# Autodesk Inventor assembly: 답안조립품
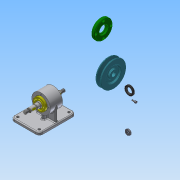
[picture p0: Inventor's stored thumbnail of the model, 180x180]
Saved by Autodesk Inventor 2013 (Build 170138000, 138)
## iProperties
Created: 2019-09
Part Number: 답안조립품
Document SubType Name: Assembly
Designer: Administrator
Author: Administrator
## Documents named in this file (10)
- C:\Users\Administrator\Desktop\490904V1052\답안조립품.iam
- C:\Users\Administrator\Desktop\490904V1052\본체.ipt
- C:\Users\Administrator\Desktop\490904V1052\V-벨트풀리.ipt
- C:\Users\Administrator\Desktop\490904V1052\너트 M10x1.ipt
- C:\Users\Administrator\Desktop\490904V1052\베어링 6004.ipt
- C:\Users\Administrator\Desktop\490904V1052\볼트 M4.ipt
- C:\Users\Administrator\Desktop\490904V1052\오일 실 17 30 5.ipt
- C:\Users\Administrator\Desktop\490904V1052\축.ipt
- C:\Users\Administrator\Desktop\490904V1052\커버.ipt
- C:\Users\Administrator\Desktop\490904V1052\키 5 x 5 x 12.ipt
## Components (2 placed, 1 different names)
1. V-벨트풀리:1
2. V-벨트풀리:2
